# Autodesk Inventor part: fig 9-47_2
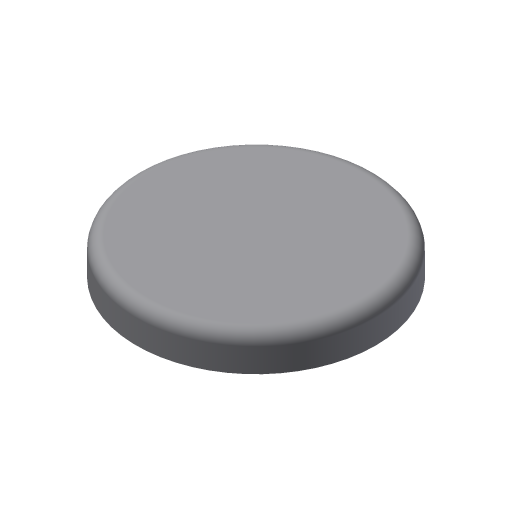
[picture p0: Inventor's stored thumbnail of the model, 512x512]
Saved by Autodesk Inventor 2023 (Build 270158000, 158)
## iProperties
Created: 2013-03
Part Number: fig 9-47_2
Material: Generic
Document SubType Name: Modeling
Designer: CADCIM
Density: 1 g/cm^3
Appearance: Default
Author: CADCIM
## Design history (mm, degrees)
sketch "Sketch1"
  geometry: C1 r 2.5 at (0, 0); 1 further point
  constraints: 1 centre point, 1 coincident
  dimensions: "d0" = 5 diameter of C1
extrude "Extrusion1" new body sketch "Sketch1" distance "d2" = 0.75; taper "d3" = 0 deg
fillet "Fillet1" dims "d4" = 0.25
body "Solid1"
